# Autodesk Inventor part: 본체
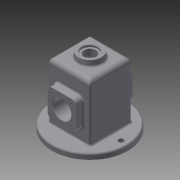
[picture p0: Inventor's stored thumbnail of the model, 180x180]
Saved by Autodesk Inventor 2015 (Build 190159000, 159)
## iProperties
Created: 2021-08
Part Number: 본체
Material: 일반
Document SubType Name: Modeling
Designer: 10462
Density: 1 g/cm^3
Appearance: 기본값
Author: 10462
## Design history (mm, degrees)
sketch "스케치1"
  geometry: C1 r 67 at (0, 0); 1 further point
  constraints: 1 centre point, 1 coincident
  dimensions: "d0" = 134 diameter of C1
extrude "돌출1" new body sketch "스케치1" distance "d1" = 10; taper "d2" = 0 deg
sketch "스케치2"
  geometry: L1 (-37, 37)-(37, 37); L2 (37, 37)-(37, -37); L3 (37, -37)-(-37, -37); L4 (-37, -37)-(-37, 37); L5 (-37, 37)-(37, -37); L6 (37, 37)-(-37, -37); C1 r 67 at (0, 0) reference
  constraints: 12 end point, 2 midpoint, 2 parallel, 1 horizontal, 1 perpendicular
  dimensions: "d3" = 74 distance of L2.end L3.end; "d4" = 74 distance of L1.end L2.end
extrude "돌출2" join sketch "스케치2" distance "d5" = 100; taper "d6" = 0 deg
sketch "스케치4"
  geometry: L1 (12, 70)-(62, 70); L2 (62, 70)-(62, 20); L3 (62, 20)-(12, 20); L4 (12, 20)-(12, 70); L5 (12, 70)-(62, 20); L6 (62, 70)-(12, 20); L7 (-30, -10)-(104, -10) reference; 3 further points
  constraints: 12 end point, 3 midpoint, 2 parallel, 1 horizontal, 1 perpendicular, 1 vertical alignment
  dimensions: "d7" = 50 distance of L1.end L2.end; "d8" = 50 distance of L2.end L3.end; "d11" = 55 distance from line of L7 point (37, 45)
extrude "돌출3" join sketch "스케치4" distance "d9" = 13; taper "d10" = 0 deg
sketch "스케치5"
  geometry: L1 (62, -70)-(12, -70); L2 (12, -70)-(12, -20); L3 (12, -20)-(62, -20); L4 (62, -20)-(62, -70); L5 (62, -70)-(12, -20); L6 (12, -70)-(62, -20); L7 (104, 10)-(-30, 10) reference; 3 further points
  constraints: 12 end point, 3 midpoint, 2 parallel, 1 horizontal, 1 perpendicular, 1 vertical alignment
  dimensions: "d12" = 50 distance of L1.end L2.end; "d13" = 50 distance of L2.end L3.end; "d14" = 55 distance from line of L7 point (37, -45)
extrude "돌출4" join sketch "스케치5" distance "d15" = 13; taper "d16" = 0 deg
fillet "모깎기1" dims "d17" = 8
sketch "스케치6"
  geometry: L1 (-32, -32)-(32, -32); L2 (32, -32)-(32, 32); L3 (32, 32)-(-32, 32); L4 (-32, 32)-(-32, -32); L5 (-32, -32)-(32, 32); L6 (32, -32)-(-32, 32); C1 r 67 at (0, 0) reference
  constraints: 12 end point, 2 midpoint, 2 parallel, 1 horizontal, 1 perpendicular
  dimensions: "d18" = 64 distance of L1.start L1.end; "d19" = 64 distance of L1.end L2.end
extrude "돌출5" cut sketch "스케치6" distance "d20" = 105; taper "d21" = 0 deg
sketch "스케치8"
  geometry: L1 (32, 0)-(32, 27.5); L2 (32, 0)-(32, 105) reference; L3 (32, 27.5)-(25, 27.5); L4 (25, 27.5)-(25, 77.5); L5 (25, 77.5)-(32, 77.5); L6 (-32, 0)-(-32, 27.5); L7 (-32, 0)-(-32, 105) reference; L8 (-32, 27.5)-(-25, 27.5); L9 (-25, 27.5)-(-25, 77.5); L10 (-25, 77.5)-(-32, 77.5); 1 further point
  constraints: 16 end point, 4 perpendicular, 4 point on line, 2 horizontal
  dimensions: "d22" = 27.5 distance of L1.start L1.end; "d23" = 7 distance of L1.end L3.end; "d24" = 50 distance of L3.end L4.end; "d25" = 27.5 distance of L6.start L6.end; "d26" = 7 distance of L6.end L8.end; "d27" = 50 distance of L8.end L9.end
extrude "돌출6" join sketch "스케치8" stored distance "d28" = 64; taper "d29" = 0 deg
sketch "스케치9"
  geometry: L1 (62, 28)-(62, 62) reference; C1 r 16 at (37, 45); 2 further points
  constraints: 1 centre point, 1 horizontal alignment, 1 midpoint, 1 vertical alignment
  dimensions: "d34" = 32 diameter of C1
hole "구멍1" sketch "스케치9" at (37, 45) diameter "d35" = 32; stored, may be unused: countersink angle "d39" = 90 deg, drill point angle "d41" = 118 deg; dims "d36" = 6, "d37" = 4, "d38" = 2, "d40" = 8
chamfer "모따기1" distance "d42" = 1; stored, may be unused: second distance "d43" = 2, angle "d44" = 45 deg
sketch "스케치10"
  geometry: C1 r 20 at (0, 0); 1 further point
  constraints: 1 centre point, 1 coincident
  dimensions: "d45" = 40 diameter of C1
extrude "돌출7" join sketch "스케치10" distance "d46" = 10; taper "d47" = 0 deg
sketch "스케치11"
  geometry: C1 r 20 at (0, 0) reference
hole "구멍2" sketch "스케치11" at (0, 0) diameter "d48" = 21; stored, may be unused: countersink angle "d52" = 90 deg, drill point angle "d54" = 118 deg; dims "d49" = 6, "d50" = 28, "d51" = 4, "d53" = 8
chamfer "모따기2" distance "d55" = 1; stored, may be unused: second distance "d56" = 2, angle "d57" = 45 deg
fillet "모깎기2" dims "d58" = 8
sketch "스케치12"
  geometry: L1 (17, -110)-(57, -110) reference; 2 further points
  constraints: 1 vertical alignment, 1 other
  dimensions: "d59" = 28 distance from line of point (37, -82) L1
feature "엠보싱1" sketch "스케치12" dims "d7" = 50, "d8" = 50, "d11" = 55, "d60" = 0.5, "d61" = 0
sketch "스케치13"
  geometry: C1 r 67 at (0, 0) reference; 2 further points
  constraints: 2 horizontal alignment
  dimensions: "d62" = 55 distance of C1.centre point (-55, 0); "d63" = 55 distance of C1.centre point (55, 0)
hole "구멍3" sketch "스케치13" at (-55, 0), (55, 0) diameter "d64" = 9; stored, may be unused: countersink angle "d68" = 90 deg, drill point angle "d70" = 118 deg; dims "d65" = 6, "d66" = 28, "d67" = 4, "d69" = 8
sketch "스케치14"
  geometry: A1 r 8 centre (20, 28) between (12, 28) and (20, 20) reference; A2 r 8 centre (54, 28) between (54, 20) and (62, 28) reference; A3 r 8 centre (54, 62) between (62, 62) and (54, 70) reference; A4 r 8 centre (20, 62) between (20, 70) and (12, 62) reference; 1 further point
hole "구멍4" sketch "스케치14" at (54, 28), (54, 62), (20, 62), (20, 28) diameter "d71" = 3.242; stored, may be unused: countersink angle "d75" = 90 deg, drill point angle "d77" = 118 deg; dims "d72" = 8, "d73" = 28, "d74" = 4, "d76" = 10
sketch "스케치15"
  geometry: A1 r 8 centre (54, -62) between (54, -70) and (62, -62) reference; A2 r 8 centre (54, -28) between (62, -28) and (54, -20) reference; A3 r 8 centre (20, -28) between (20, -20) and (12, -28) reference; A4 r 8 centre (20, -62) between (12, -62) and (20, -70) reference; 1 further point
hole "구멍5" sketch "스케치15" at (54, -62), (20, -62), (20, -28), (54, -28) diameter "d78" = 3.242; stored, may be unused: countersink angle "d82" = 90 deg, drill point angle "d84" = 118 deg; dims "d79" = 8, "d80" = 28, "d81" = 4, "d83" = 10
fillet "모깎기3" dims "d85" = 3
fillet "모깎기4" dims "d86" = 3
fillet "모깎기5" dims "d87" = 3
fillet "모깎기6" dims "d88" = 3
fillet "모깎기7" dims "d89" = 3
fillet "모깎기8" dims "d90" = 3
feature "면 기울기5" dims angle "d92" = 20 deg
feature "면 기울기6" dims angle "d93" = 20 deg
feature "면 기울기7" dims angle "d94" = 20 deg
feature "면 기울기8" dims angle "d95" = 20 deg
feature "면 기울기9" dims angle "d96" = 6 deg
fillet "모깎기10" dims "d97" = 3
node "솔리드1"
